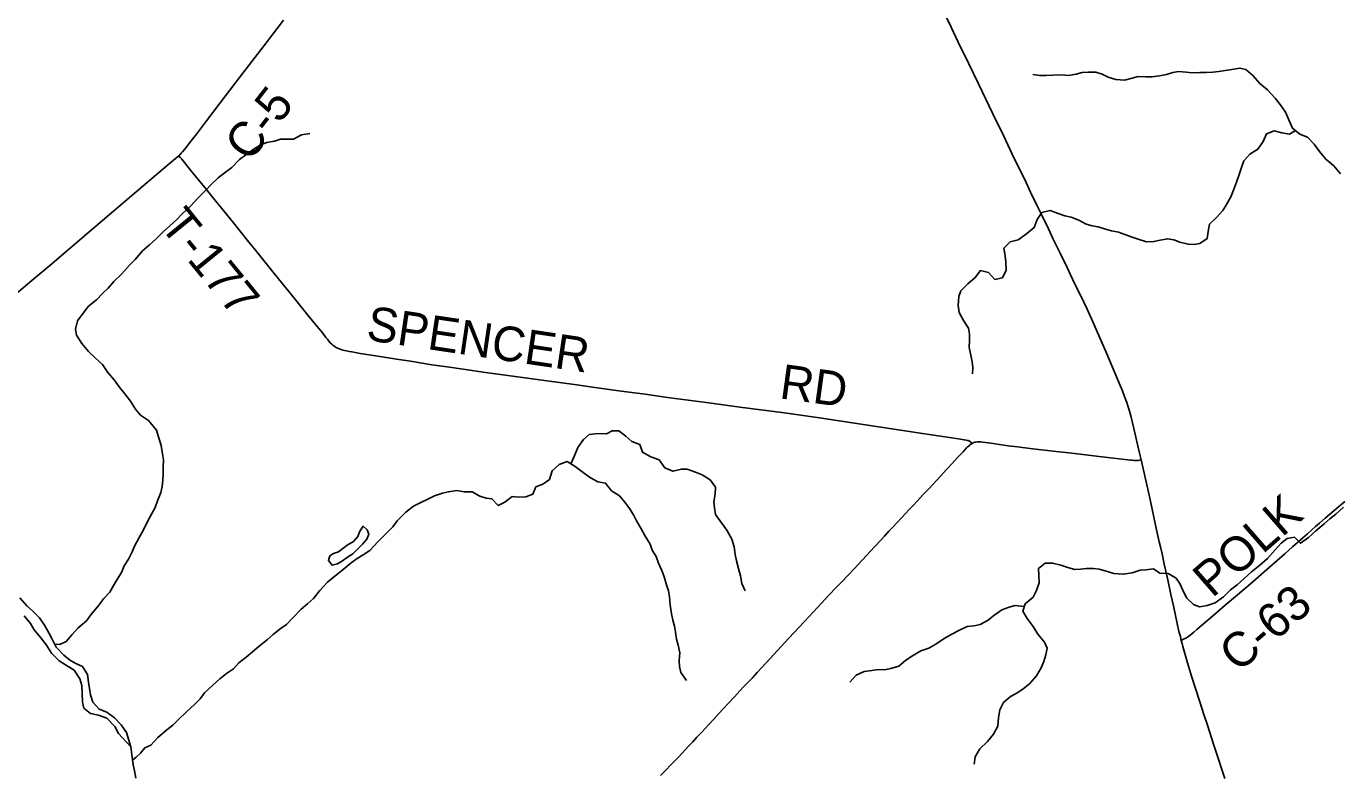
# Model space of a CAD drawing. Extents: x 1442749 to 1756758, y 235267 to 677782.
# Drawn here: x 1623834 to 1635226, y 548463 to 554957 of the extents above; entities that cross this region are included whole.
import ezdxf

# ---------------------------------------------------------------- set-up
doc = ezdxf.new("R2010")
doc.units = 0
for name, color, linetype in [('GM_X_County_Road', 7, 'Continuous'), ('GM_X_County_Road_Text', 7, 'Continuous'), ('GM_X_Major_River', 7, 'Continuous'), ('GM_X_Minor_Lake', 7, 'Continuous'), ('GM_X_Minor_River', 7, 'Continuous'), ('GM_X_State_Route', 7, 'Continuous'), ('GM_X_Township_Road', 7, 'Continuous'), ('GM_X_Township_Road_Text', 7, 'Continuous')]:
    doc.layers.add(name, color=color, linetype=linetype)

msp = doc.modelspace()

# ---------------------------------------------------------------- linework, layer by layer
at = {"layer": 'GM_X_County_Road'}
for points in [[(1625156, 553833), (1625166, 553843), (1625178, 553856), (1625190, 553869), (1625204, 553885), (1625217, 553901), (1625227, 553914), (1625254, 553948), (1625311, 554022), (1625353, 554079), (1625396, 554136), (1625516, 554292), (1625683, 554512), (1625898, 554790), (1626065, 555009)], [(1623658, 552561), (1623882, 552750), (1624039, 552882), (1624418, 553206), (1624787, 553521), (1625019, 553718), (1625127, 553809), (1625156, 553833)], [(1629335, 548456), (1629361, 548483), (1629391, 548512), (1629417, 548539), (1629443, 548566), (1629467, 548592), (1629493, 548618), (1629518, 548645), (1629552, 548681), (1629582, 548714), (1629615, 548749), (1629651, 548788), (1629690, 548829), (1629721, 548863), (1629754, 548898), (1629795, 548943), (1629841, 548994), (1629882, 549038), (1629920, 549079), (1629976, 549140), (1630023, 549190), (1630059, 549228), (1630133, 549305), (1630174, 549350), (1630212, 549391), (1630251, 549434), (1630449, 549649), (1630583, 549792), (1630698, 549915), (1630799, 550023), (1630857, 550084), (1630908, 550137), (1630961, 550193), (1631014, 550249), (1631157, 550403), (1631277, 550533), (1631315, 550575), (1631352, 550615), (1631385, 550650), (1631427, 550694), (1631492, 550763), (1631526, 550799), (1631564, 550839), (1631614, 550894), (1631661, 550944), (1631765, 551056), (1631813, 551108), (1631865, 551164), (1631912, 551215), (1631935, 551240), (1631959, 551265), (1631976, 551283), (1631990, 551298), (1631999, 551307), (1632008, 551315), (1632016, 551323), (1632023, 551328), (1632031, 551334), (1632038, 551338)], [(1632038, 551338), (1632044, 551341), (1632052, 551345), (1632061, 551348), (1632071, 551350), (1632081, 551351), (1632091, 551351), (1632101, 551351), (1632114, 551351), (1632131, 551349), (1632154, 551346), (1632201, 551339), (1632351, 551317), (1632430, 551307), (1632497, 551299), (1632565, 551291), (1632741, 551270), (1632904, 551252), (1633020, 551238), (1633188, 551219), (1633387, 551196), (1633413, 551193), (1633427, 551191), (1633443, 551190), (1633457, 551190), (1633468, 551190), (1633479, 551190), (1633491, 551192), (1633503, 551195)], [(1633852, 549629), (1633865, 549635), (1633878, 549641), (1633887, 549645), (1633898, 549652), (1633906, 549657), (1633917, 549665), (1633930, 549675), (1633944, 549687), (1633961, 549700), (1633986, 549723), (1634026, 549757), (1634066, 549791), (1634142, 549855), (1634234, 549934), (1634341, 550023), (1634452, 550119), (1634617, 550263), (1634749, 550379), (1634818, 550440), (1634860, 550477), (1634905, 550518), (1634946, 550554), (1634985, 550588), (1635017, 550617), (1635051, 550646), (1635100, 550688), (1635272, 550835)]]:
    msp.add_lwpolyline(points, dxfattribs=at)
at = {"layer": 'GM_X_Major_River'}
for points in [[(1624742, 548706), (1624704, 548829), (1624658, 548897), (1624598, 548957), (1624533, 549005), (1624465, 549032), (1624411, 549092), (1624391, 549156), (1624383, 549212), (1624375, 549266), (1624365, 549333), (1624321, 549401), (1624259, 549431), (1624209, 549459), (1624159, 549501), (1624093, 549570), (1624059, 549638), (1624033, 549688), (1623992, 549762), (1623950, 549824), (1623888, 549885), (1623838, 549929), (1623778, 549999)], [(1623816, 549843), (1623870, 549774), (1623902, 549720), (1623960, 549652), (1624010, 549588), (1624054, 549519), (1624118, 549451), (1624197, 549401), (1624249, 549369), (1624299, 549296), (1624315, 549238), (1624319, 549170), (1624323, 549094)], [(1624323, 549094), (1624333, 549042), (1624391, 548993), (1624459, 548981), (1624533, 548953), (1624601, 548881), (1624635, 548821), (1624742, 548706)], [(1624742, 548706), (1624760, 548548), (1624774, 548496), (1624784, 548434)]]:
    msp.add_lwpolyline(points, dxfattribs=at)
at = {"layer": 'GM_X_Minor_Lake'}
for points in [[(1626673, 550385), (1626704, 550417), (1626749, 550463), (1626787, 550507), (1626806, 550551), (1626790, 550589), (1626756, 550619), (1626728, 550577), (1626709, 550531), (1626672, 550488), (1626617, 550456)], [(1626617, 550456), (1626541, 550396), (1626498, 550383), (1626468, 550361), (1626454, 550321), (1626487, 550281), (1626534, 550292), (1626578, 550318), (1626621, 550350), (1626667, 550379), (1626673, 550385)]]:
    msp.add_lwpolyline(points, dxfattribs=at)
at = {"layer": 'GM_X_Minor_River'}
for points in [[(1635234, 553676), (1635175, 553747), (1635105, 553804), (1635051, 553870), (1635005, 553933), (1634948, 553996), (1634880, 554021), (1634816, 554073), (1634786, 554144), (1634755, 554213), (1634711, 554279), (1634666, 554334), (1634600, 554407), (1634534, 554462), (1634473, 554530), (1634413, 554583), (1634361, 554594), (1634290, 554582), (1634234, 554573), (1634177, 554565), (1634125, 554560), (1634067, 554556), (1634014, 554555), (1633946, 554553), (1633894, 554558), (1633829, 554565), (1633779, 554557), (1633725, 554539), (1633662, 554528), (1633596, 554517), (1633545, 554517), (1633477, 554522), (1633427, 554506), (1633360, 554489), (1633284, 554495), (1633217, 554516), (1633165, 554541), (1633111, 554559), (1633043, 554558), (1632993, 554556), (1632940, 554543), (1632872, 554531), (1632813, 554536), (1632737, 554533), (1632677, 554529), (1632626, 554530), (1632564, 554538)], [(1624080, 549595), (1624125, 549592), (1624180, 549618), (1624231, 549681), (1624282, 549735), (1624355, 549797), (1624394, 549850), (1624463, 549934), (1624506, 549992), (1624558, 550048), (1624587, 550100), (1624624, 550164), (1624661, 550219), (1624683, 550275), (1624720, 550333), (1624753, 550397), (1624774, 550447), (1624811, 550515), (1624850, 550589), (1624886, 550659), (1624921, 550725), (1624952, 550781), (1624973, 550839), (1625002, 550913), (1625014, 550965), (1625017, 551019), (1625021, 551075), (1625022, 551134), (1625025, 551194), (1625013, 551264), (1625004, 551320), (1624978, 551403), (1624963, 551453), (1624895, 551536), (1624825, 551583), (1624782, 551636), (1624738, 551704), (1624689, 551767), (1624641, 551828), (1624597, 551888), (1624542, 551953), (1624494, 552022), (1624432, 552081), (1624373, 552136), (1624317, 552204), (1624271, 552277), (1624260, 552329), (1624279, 552401), (1624326, 552469), (1624375, 552529), (1624444, 552583), (1624494, 552638), (1624545, 552684), (1624594, 552742), (1624659, 552807), (1624728, 552885), (1624779, 552933), (1624842, 553008), (1624903, 553062), (1624960, 553114), (1625025, 553177), (1625078, 553225), (1625138, 553279), (1625185, 553331), (1625258, 553396), (1625325, 553470), (1625388, 553533), (1625441, 553587), (1625498, 553641), (1625563, 553692), (1625616, 553732), (1625683, 553800), (1625739, 553843), (1625802, 553887), (1625865, 553928), (1625921, 553950), (1625988, 553961), (1626038, 553979), (1626089, 553977), (1626151, 553978), (1626220, 554016), (1626292, 554027)], [(1634842, 554052), (1634791, 554021), (1634725, 554032), (1634657, 554051), (1634590, 554025), (1634561, 553957), (1634516, 553890), (1634448, 553848), (1634395, 553790), (1634378, 553740), (1634353, 553672), (1634332, 553604), (1634306, 553536), (1634281, 553476), (1634244, 553410), (1634211, 553358), (1634158, 553297), (1634097, 553241), (1634085, 553177), (1634076, 553115), (1634013, 553071), (1633963, 553063), (1633911, 553066), (1633840, 553085), (1633786, 553105), (1633734, 553114), (1633670, 553102), (1633615, 553089), (1633551, 553087), (1633479, 553110), (1633427, 553127), (1633370, 553147), (1633308, 553170), (1633248, 553181), (1633186, 553199), (1633132, 553216), (1633080, 553226), (1633027, 553241), (1632963, 553276), (1632897, 553302), (1632841, 553311), (1632785, 553332), (1632715, 553360), (1632642, 553341), (1632602, 553281), (1632575, 553211), (1632510, 553155), (1632437, 553104), (1632368, 553088), (1632313, 553033), (1632323, 552964), (1632330, 552912), (1632334, 552842), (1632301, 552774), (1632236, 552760), (1632179, 552821), (1632110, 552838), (1632065, 552778), (1632001, 552722), (1631940, 552663), (1631923, 552613), (1631918, 552533), (1631926, 552474), (1631963, 552404), (1632005, 552339), (1632016, 552285), (1632014, 552234), (1632013, 552170), (1632026, 552102), (1632038, 552046), (1632045, 551995), (1632041, 551941)], [(1628557, 551161), (1628586, 551225), (1628619, 551301), (1628666, 551372), (1628717, 551416), (1628794, 551423), (1628866, 551421), (1628917, 551448), (1628975, 551446), (1629035, 551401), (1629087, 551354), (1629155, 551328), (1629178, 551261), (1629252, 551220), (1629322, 551194), (1629372, 551127), (1629442, 551096), (1629516, 551115), (1629567, 551115), (1629639, 551088), (1629697, 551066), (1629767, 551021), (1629813, 550958), (1629810, 550898), (1629797, 550830), (1629803, 550779), (1629812, 550721), (1629864, 550650), (1629911, 550584), (1629955, 550507), (1629974, 550439), (1629982, 550374), (1629993, 550320), (1630012, 550253), (1630028, 550189), (1630041, 550123), (1630069, 550058)], [(1624826, 548649), (1624862, 548696), (1624915, 548721), (1624976, 548785), (1625053, 548852), (1625104, 548894), (1625157, 548944), (1625222, 549007), (1625293, 549071), (1625343, 549121), (1625380, 549173), (1625451, 549240), (1625512, 549294), (1625571, 549341), (1625630, 549381), (1625678, 549433), (1625741, 549482), (1625796, 549528), (1625855, 549580), (1625926, 549637), (1625976, 549679), (1626035, 549729), (1626090, 549766), (1626147, 549824), (1626218, 549900), (1626273, 549947), (1626324, 549993), (1626379, 550063), (1626446, 550134), (1626509, 550186), (1626582, 550244), (1626652, 550301), (1626703, 550339), (1626756, 550372), (1626814, 550410), (1626884, 550484), (1626949, 550549), (1627012, 550615), (1627050, 550667), (1627126, 550740), (1627192, 550794), (1627261, 550827), (1627312, 550851), (1627376, 550883), (1627443, 550906), (1627495, 550918), (1627568, 550929), (1627632, 550918), (1627700, 550918), (1627768, 550879), (1627823, 550864), (1627873, 550858), (1627927, 550799), (1627985, 550827), (1628048, 550876), (1628100, 550872), (1628167, 550873), (1628229, 550897), (1628254, 550961), (1628315, 550984), (1628373, 551026), (1628396, 551100), (1628457, 551156), (1628526, 551181), (1628594, 551138), (1628665, 551085), (1628719, 551045), (1628791, 551004), (1628858, 550993), (1628911, 550926), (1628979, 550882), (1629025, 550829), (1629065, 550772), (1629102, 550718), (1629126, 550665), (1629163, 550603), (1629199, 550538), (1629246, 550463), (1629262, 550411), (1629296, 550357), (1629319, 550298), (1629347, 550236), (1629368, 550179), (1629388, 550111), (1629403, 550060), (1629413, 550008), (1629418, 549936), (1629431, 549859), (1629443, 549805), (1629456, 549751), (1629466, 549700), (1629475, 549638), (1629487, 549588), (1629504, 549521), (1629498, 549453), (1629499, 549401), (1629511, 549349), (1629560, 549280)], [(1635259, 550786), (1635192, 550723), (1635141, 550683), (1635091, 550639), (1635020, 550578), (1634955, 550520), (1634886, 550471), (1634834, 550523), (1634769, 550512), (1634719, 550472), (1634666, 550413), (1634601, 550339), (1634534, 550281), (1634461, 550224), (1634396, 550166), (1634337, 550110), (1634280, 550067), (1634219, 550007), (1634146, 549954), (1634076, 549930), (1634009, 549921), (1633959, 549939), (1633899, 549994), (1633872, 550049), (1633842, 550117), (1633807, 550168), (1633737, 550208), (1633666, 550213), (1633610, 550250), (1633544, 550242), (1633494, 550237), (1633425, 550215), (1633348, 550202), (1633268, 550209), (1633192, 550232), (1633140, 550246), (1633090, 550253), (1633029, 550251), (1632979, 550246), (1632929, 550244), (1632876, 550259), (1632808, 550281), (1632736, 550300), (1632670, 550299), (1632615, 550253), (1632616, 550193), (1632618, 550129), (1632593, 550057), (1632566, 550003), (1632497, 549947), (1632478, 549883), (1632514, 549820), (1632568, 549750), (1632609, 549683), (1632667, 549614), (1632688, 549560), (1632678, 549504), (1632661, 549446), (1632638, 549392), (1632597, 549322), (1632536, 549252), (1632482, 549208), (1632427, 549171), (1632370, 549141), (1632309, 549091), (1632277, 549026), (1632268, 548959), (1632261, 548883), (1632222, 548815), (1632171, 548751), (1632106, 548688)], [(1632490, 549922), (1632412, 549932), (1632360, 549916), (1632295, 549893), (1632227, 549845), (1632176, 549803), (1632107, 549766), (1632055, 549756), (1631996, 549749), (1631922, 549714), (1631863, 549682), (1631794, 549644), (1631723, 549597), (1631661, 549561), (1631594, 549538), (1631521, 549496), (1631464, 549457), (1631402, 549405), (1631333, 549386), (1631275, 549374), (1631222, 549375), (1631168, 549367), (1631101, 549358), (1631031, 549326), (1630976, 549267)], [(1632106, 548688), (1632065, 548618), (1632057, 548554)], [(1624756, 548588), (1624786, 548616), (1624826, 548649)]]:
    msp.add_lwpolyline(points, dxfattribs=at)
at = {"layer": 'GM_X_State_Route'}
msp.add_lwpolyline([(1634231, 548430), (1634199, 548526), (1634178, 548589), (1634132, 548729), (1634078, 548894), (1634049, 548985), (1634014, 549097), (1633941, 549319), (1633906, 549435), (1633865, 549577), (1633859, 549601), (1633852, 549629), (1633844, 549661), (1633832, 549707), (1633817, 549774), (1633784, 549928), (1633762, 550027), (1633734, 550155), (1633704, 550290), (1633685, 550379), (1633671, 550440), (1633661, 550485), (1633638, 550587), (1633576, 550876), (1633538, 551042), (1633503, 551195), (1633489, 551253), (1633440, 551467), (1633413, 551576), (1633408, 551597), (1633402, 551618), (1633396, 551639), (1633388, 551665), (1633379, 551693), (1633369, 551721), (1633360, 551745), (1633344, 551786), (1633333, 551813), (1633322, 551840), (1633207, 552115), (1633097, 552368), (1633035, 552502), (1632977, 552624), (1632933, 552715), (1632892, 552801), (1632859, 552869), (1632803, 552984), (1632770, 553052), (1632742, 553111), (1632699, 553199), (1632644, 553311), (1632598, 553406), (1632544, 553518), (1632494, 553627), (1632427, 553763), (1632383, 553852), (1632312, 554003), (1632218, 554198), (1632093, 554458), (1632010, 554630), (1631918, 554819), (1631855, 554948), (1631766, 555131)], dxfattribs=at)
at = {"layer": 'GM_X_Township_Road'}
msp.add_lwpolyline([(1625156, 553833), (1625169, 553819), (1625183, 553803), (1625206, 553776), (1625259, 553710), (1625394, 553543), (1625464, 553456), (1625530, 553375), (1625630, 553252), (1625698, 553168), (1625753, 553099), (1625821, 553015), (1625984, 552813), (1626084, 552688), (1626136, 552624), (1626229, 552509), (1626276, 552450), (1626357, 552352), (1626405, 552293), (1626432, 552258), (1626446, 552241), (1626459, 552225), (1626471, 552211), (1626483, 552200), (1626492, 552191), (1626501, 552183), (1626512, 552175), (1626521, 552170), (1626533, 552164), (1626543, 552160), (1626556, 552155), (1626566, 552152), (1626580, 552148), (1626595, 552144), (1626611, 552141), (1626634, 552136), (1626660, 552131), (1626687, 552126), (1626731, 552119), (1626867, 552097), (1627044, 552069), (1627167, 552050), (1627352, 552021), (1627485, 552001), (1627622, 551982), (1627816, 551954), (1628010, 551927), (1628393, 551875), (1628588, 551848), (1628765, 551823), (1628994, 551792), (1629203, 551764), (1629396, 551737), (1629754, 551689), (1630023, 551652), (1630410, 551602), (1630714, 551560), (1631247, 551480), (1631606, 551425), (1631919, 551377), (1631970, 551369), (1631986, 551366), (1631997, 551364), (1632003, 551362), (1632008, 551361), (1632012, 551359), (1632016, 551356), (1632021, 551353), (1632028, 551347), (1632033, 551343), (1632038, 551338)], dxfattribs=at)

# ---------------------------------------------------------------- texts
at = {"layer": 'GM_X_County_Road_Text'}
for s, rotation, p in [('C-5', 52.3196, (1625771, 553769)), ('POLK', 41.0662, (1634120, 549991)), ('C-63', 40.6781, (1634346, 549342))]:
    msp.add_text(s, height=300, rotation=rotation, dxfattribs=at).set_placement(p)
at = {"layer": 'GM_X_Township_Road_Text'}
for s, rotation, p in [('T-177', 309.1354, (1624983, 553226)), ('SPENCER', 351.5441, (1626775, 552236)), ('RD', 352.1419, (1630359, 551730))]:
    msp.add_text(s, height=300, rotation=rotation, dxfattribs=at).set_placement(p)

doc.saveas('drawing.dxf')
